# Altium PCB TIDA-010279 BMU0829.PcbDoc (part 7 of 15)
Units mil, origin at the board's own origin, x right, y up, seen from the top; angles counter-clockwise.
Board outline 11269.69 x 4438.98 mil, 4 copper layers (Top Layer, Signal Layer 1, Signal Layer 2, Bottom Layer), stack 61.6 mil thick; 1494 components, 725 nets, 3766 pads, 2728 vias.
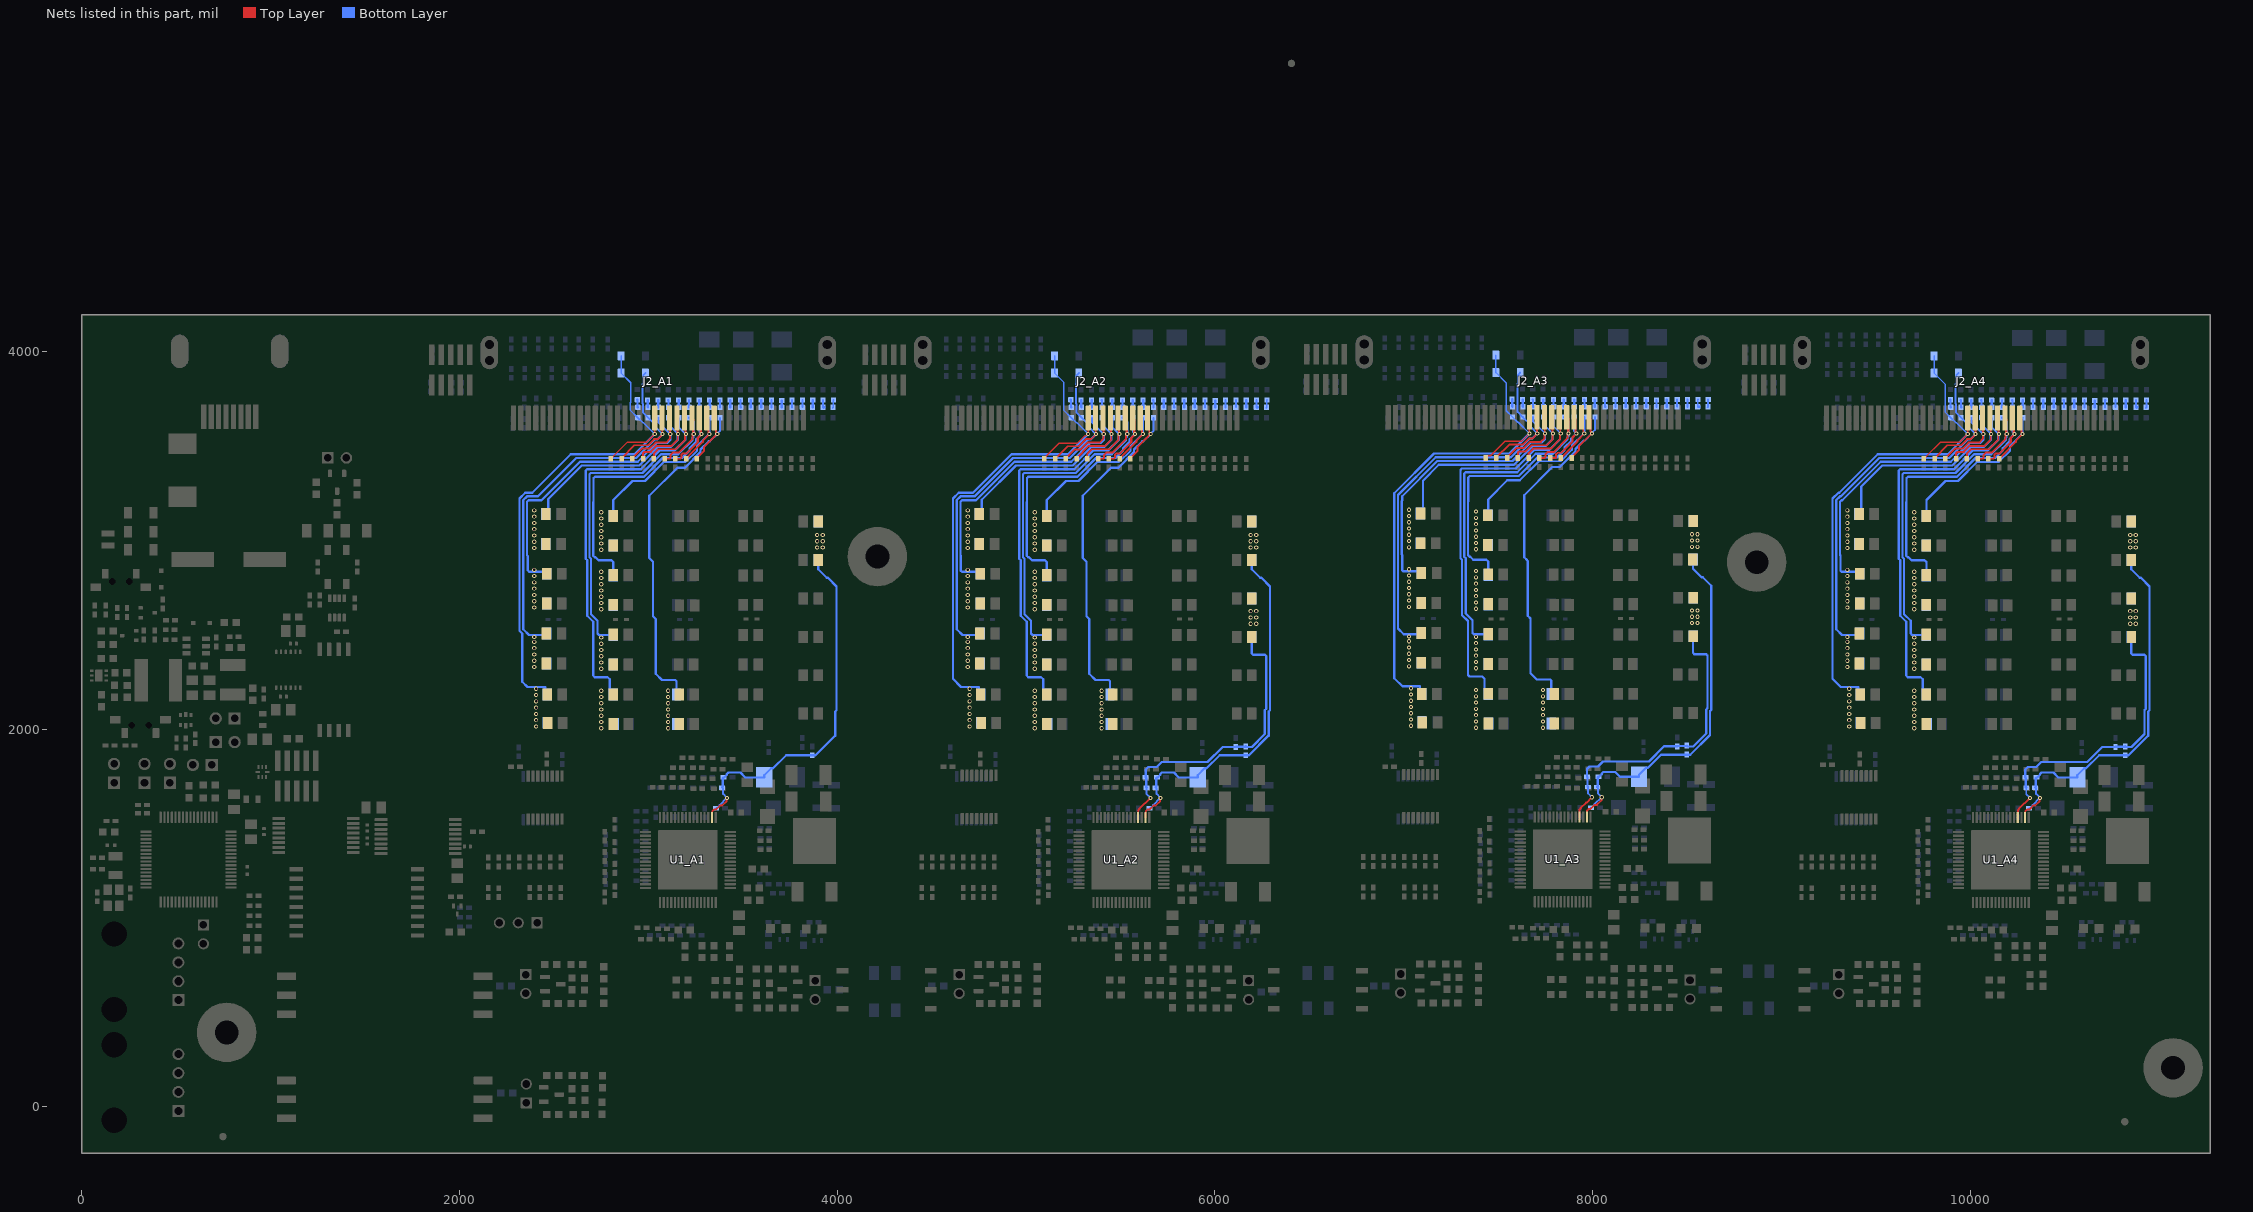
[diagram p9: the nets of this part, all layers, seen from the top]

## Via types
v1: diameter 22.01, hole 12.01, Top Layer to Bottom Layer, tented both sides, 2578 vias
v2: diameter 19.68, hole 7.87, Top Layer to Bottom Layer, tented both sides, 144 vias
v3: diameter 92.52, hole 49.21, Top Layer to Bottom Layer, 4 vias
v4: diameter 19.68, hole 7.87, Top Layer to Bottom Layer, 2 vias

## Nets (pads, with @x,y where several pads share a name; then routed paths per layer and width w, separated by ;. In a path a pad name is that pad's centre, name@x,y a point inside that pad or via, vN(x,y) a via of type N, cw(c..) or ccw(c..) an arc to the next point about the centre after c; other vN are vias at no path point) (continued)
CB17_A2: C4_A2.2 C17_A2.1 R15_A2.2 R18_A2.2 R22_A2.2 R25_A2.2 R198_A2.2 R203_A2.1 U1_A2.4 | length 1594.2
  Top Layer w10: U1_A2.4@5593.07,1531.37 5593.97,1532.27 5593.97,1570.71 5599.59,1576.34 5599.59,1579.06 5628.05,1607.51 5630.77,1607.51 v1(5658.86,1635.6)
  Bottom Layer w10: C4_A2.2@5638.39,1690.14 5638.39,1656.07 v1(5658.86,1635.6)
  Bottom Layer w12: C4_A2.2@5638.39,1690.14 5635.88,1692.66 5635.88,1741.49 C17_A2.1@5633.37,1744.01 5633.37,1785.65 5646.48,1798.76 5691.61,1798.76 5718.36,1825.5 5960.79,1825.5 6040.67,1905.38 R203_A2.1@6110.97,1905.38 6112.65,1907.06 6160.62,1907.06 R198_A2.2@6162.3,1908.75 6162.3,1905 6195.54,1905 6264.19,1973.65 6264.19,2100.78 6271.38,2107.97 6271.38,2386.52 6264.35,2393.55 6201.5,2393.55 6194.47,2400.58 R18_A2.2@6194.47,2488.51
  other v1: 6188.77,2558.04 6218.3,2558.04 6188.77,2591.22 6218.3,2591.22 6188.77,2624.41 6218.3,2624.41
CB17_A3: C4_A3.2 C17_A3.1 R15_A3.2 R18_A3.2 R22_A3.2 R25_A3.2 R198_A3.2 R203_A3.1 U1_A3.4 | length 1594.2
  Top Layer w10: U1_A3.4@7929.66,1534.57 7930.57,1535.48 7930.57,1573.92 7936.19,1579.54 7936.19,1582.27 7964.64,1610.72 7967.37,1610.72 v1(7995.46,1638.81)
  Bottom Layer w10: C4_A3.2@7974.99,1693.35 7974.99,1659.28 v1(7995.46,1638.81)
  Bottom Layer w12: C4_A3.2@7974.99,1693.35 7972.48,1695.86 7972.48,1744.7 C17_A3.1@7969.96,1747.21 7969.96,1788.86 7983.07,1801.96 8028.2,1801.96 8054.95,1828.71 8297.39,1828.71 8377.27,1908.59 R203_A3.1@8447.57,1908.59 8449.25,1910.27 8497.21,1910.27 R198_A3.2@8498.9,1911.96 8498.9,1908.21 8532.14,1908.21 8600.79,1976.86 8600.79,2103.99 8607.98,2111.18 8607.98,2389.73 8600.95,2396.75 8538.09,2396.75 8531.06,2403.78 R18_A3.2@8531.06,2491.72
  other v1: 8525.37,2561.24 8554.9,2561.24 8525.37,2594.43 8554.9,2594.43 8525.37,2627.61 8554.9,2627.61
CB17_A4: C4_A4.2 C17_A4.1 R15_A4.2 R18_A4.2 R22_A4.2 R25_A4.2 R198_A4.2 R203_A4.1 U1_A4.4 | length 1594.2
  Top Layer w10: U1_A4.4@10249.89,1531.37 10250.8,1532.27 10250.8,1570.71 10256.42,1576.34 10256.42,1579.06 10284.87,1607.51 10287.6,1607.51 v1(10315.69,1635.6)
  Bottom Layer w10: C4_A4.2@10295.22,1690.14 10295.22,1656.07 v1(10315.69,1635.6)
  Bottom Layer w12: C4_A4.2@10295.22,1690.14 10292.71,1692.66 10292.71,1741.49 C17_A4.1@10290.19,1744.01 10290.19,1785.65 10303.3,1798.76 10348.43,1798.76 10375.18,1825.5 10617.62,1825.5 10697.5,1905.38 R203_A4.1@10767.8,1905.38 10769.48,1907.06 10817.44,1907.06 R198_A4.2@10819.13,1908.75 10819.13,1905 10852.37,1905 10921.02,1973.65 10921.02,2100.78 10928.21,2107.97 10928.21,2386.52 10921.18,2393.55 10858.32,2393.55 10851.29,2400.58 R18_A4.2@10851.29,2488.51
  other v1: 10845.6,2558.04 10875.13,2558.04 10845.6,2591.22 10875.13,2591.22 10845.6,2624.41 10875.13,2624.41
CB18_A1: C1_A1.1 C4_A1.1 D10_A1.1 R3_A1.2 R6_A1.2 R9_A1.2 R12_A1.2 R198_A1.1 R204_A1.2 U1_A1.2 | length 2044.2
  Top Layer w10: U1_A1.2@3337.42,1531.37 3337.42,1554.99 3338.33,1555.89 3338.33,1565.08 3347.01,1573.77 3358.1,1573.77 3379.79,1595.46 3390.88,1595.46 3414.12,1618.69 3414.12,1633.3 v1(3416.41,1635.6)
  Bottom Layer w10: R204_A1.2@3358.56,1580.59 3362.5,1580.59 3377.18,1595.27 3377.18,1597.73 3415.05,1635.6 v1(3416.41,1635.6) 3395.62,1656.39 3395.62,1685.14 C4_A1.1@3390.62,1690.14
  Bottom Layer w12: C4_A1.1@3390.62,1690.14 3394.32,1693.84 3394.32,1740.32 C1_A1.1@3398.02,1744.01 3401.95,1744.01 3415.64,1757.7 3415.64,1761.57 3423.77,1769.7 3487.57,1769.7 3513.39,1743.88 3613.56,1743.88 D10_A1.1@3613.69,1744.01 3613.69,1755.51 3650.19,1792.01 3660.39,1792.01 3729.88,1861.5 R198_A1.1@3867.28,1861.5 3885.14,1861.5 3989.05,1965.42 3989.05,2092.55 3996.24,2099.74 3996.24,2755.55 3951.17,2800.62 3944.52,2800.62 3899.45,2845.69 R3_A1.2@3899.45,2895.38
  other v1: 3893.76,2961.58 3923.29,2961.58 3893.76,2994.76 3923.29,2994.76 3893.76,3027.95 3923.29,3027.95
CB18_A2: C1_A2.1 C4_A2.1 D10_A2.1 R3_A2.2 R6_A2.2 R9_A2.2 R12_A2.2 R198_A2.1 R204_A2.2 U1_A2.2 | length 2044.2
  Top Layer w10: U1_A2.2@5632.44,1531.37 5632.44,1554.99 5633.34,1555.89 5633.34,1565.08 5642.02,1573.77 5653.12,1573.77 5674.81,1595.46 5685.9,1595.46 5709.13,1618.69 5709.13,1633.3 v1(5711.43,1635.6)
  Bottom Layer w10: R204_A2.2@5653.58,1580.59 5657.51,1580.59 5672.2,1595.27 5672.2,1597.73 5710.07,1635.6 v1(5711.43,1635.6) 5690.64,1656.39 5690.64,1685.14 C4_A2.1@5685.64,1690.14
  Bottom Layer w12: C4_A2.1@5685.64,1690.14 5689.33,1693.84 5689.33,1740.32 C1_A2.1@5693.03,1744.01 5696.97,1744.01 5710.65,1757.7 5710.65,1761.57 5718.78,1769.7 5782.59,1769.7 5808.4,1743.88 5908.58,1743.88 D10_A2.1@5908.7,1744.01 5908.71,1755.51 5945.21,1792.01 5955.41,1792.01 6024.9,1861.5 R198_A2.1@6162.3,1861.5 6180.15,1861.5 6284.06,1965.42 6284.06,2092.55 6291.26,2099.74 6291.26,2755.55 6246.19,2800.62 6239.54,2800.62 6194.47,2845.69 R3_A2.2@6194.47,2895.38
  other v1: 6188.77,2961.58 6218.3,2961.58 6188.77,2994.76 6218.3,2994.76 6188.77,3027.95 6218.3,3027.95
CB18_A3: C1_A3.1 C4_A3.1 D10_A3.1 R3_A3.2 R6_A3.2 R9_A3.2 R12_A3.2 R198_A3.1 R204_A3.2 U1_A3.2 | length 2044.2
  Top Layer w10: U1_A3.2@7969.03,1534.57 7969.03,1558.2 7969.94,1559.1 7969.94,1568.29 7978.62,1576.97 7989.71,1576.97 8011.4,1598.66 8022.5,1598.66 8045.73,1621.9 8045.73,1636.51 v1(8048.03,1638.81)
  Bottom Layer w10: R204_A3.2@7990.17,1583.79 7994.11,1583.79 8008.79,1598.48 8008.79,1600.94 8046.67,1638.81 v1(8048.03,1638.81) 8027.23,1659.6 8027.23,1688.35 C4_A3.1@8022.23,1693.35
  Bottom Layer w12: C4_A3.1@8022.23,1693.35 8025.93,1697.05 8025.93,1743.53 C1_A3.1@8029.63,1747.22 8033.57,1747.22 8047.25,1760.91 8047.25,1764.78 8055.38,1772.91 8119.18,1772.91 8145,1747.09 8245.18,1747.09 D10_A3.1@8245.3,1747.22 8245.31,1758.72 8281.81,1795.22 8292,1795.22 8361.5,1864.71 R198_A3.1@8498.9,1864.71 8516.75,1864.71 8620.66,1968.62 8620.66,2095.76 8627.85,2102.95 8627.85,2758.76 8582.79,2803.83 8576.13,2803.83 8531.06,2848.89 R3_A3.2@8531.06,2898.58
  other v1: 8525.37,2964.79 8554.9,2964.79 8525.37,2997.97 8554.9,2997.97 8525.37,3031.16 8554.9,3031.16
CB18_A4: C1_A4.1 C4_A4.1 D10_A4.1 R3_A4.2 R6_A4.2 R9_A4.2 R12_A4.2 R198_A4.1 R204_A4.2 U1_A4.2 | length 2044.2
  Top Layer w10: U1_A4.2@10289.26,1531.37 10289.26,1554.99 10290.17,1555.89 10290.17,1565.08 10298.85,1573.77 10309.94,1573.77 10331.63,1595.46 10342.73,1595.46 10365.96,1618.69 10365.96,1633.3 v1(10368.26,1635.6)
  Bottom Layer w10: R204_A4.2@10310.4,1580.59 10314.34,1580.59 10329.02,1595.27 10329.02,1597.73 10366.89,1635.6 v1(10368.26,1635.6) 10347.46,1656.39 10347.46,1685.14 C4_A4.1@10342.46,1690.14
  Bottom Layer w12: C4_A4.1@10342.46,1690.14 10346.16,1693.84 10346.16,1740.32 C1_A4.1@10349.86,1744.01 10353.8,1744.01 10367.48,1757.7 10367.48,1761.57 10375.61,1769.7 10439.41,1769.7 10465.23,1743.88 10565.41,1743.88 D10_A4.1@10565.53,1744.01 10565.54,1755.51 10602.04,1792.01 10612.23,1792.01 10681.73,1861.5 R198_A4.1@10819.13,1861.5 10836.98,1861.5 10940.89,1965.42 10940.89,2092.55 10948.08,2099.74 10948.08,2755.55 10903.02,2800.62 10896.36,2800.62 10851.29,2845.69 R3_A4.2@10851.29,2895.38
  other v1: 10845.6,2961.58 10875.13,2961.58 10845.6,2994.76 10875.13,2994.76 10845.6,3027.95 10875.13,3027.95
CCAP_0_A1: C91_A1.2 C92_A1.1 | length 40.9
  Bottom Layer w12: C92_A1.1@2941.7,3743.58 2942.97,3742.31 2942.97,3704.97 C91_A1.2@2944.24,3703.7
CCAP_0_A2: C91_A2.2 C92_A2.1 | length 40.9
  Bottom Layer w12: C92_A2.1@5236.71,3743.58 5237.98,3742.31 5237.98,3704.97 C91_A2.2@5239.25,3703.7
CCAP_0_A3: C91_A3.2 C92_A3.1 | length 40.9
  Bottom Layer w12: C92_A3.1@7573.31,3746.79 7574.58,3745.52 7574.58,3708.17 C91_A3.2@7575.85,3706.9
CCAP_0_A4: C91_A4.2 C92_A4.1 | length 40.9
  Bottom Layer w12: C92_A4.1@9893.54,3743.58 9894.81,3742.31 9894.81,3704.97 C91_A4.2@9896.08,3703.7
CCAP_1_A1: C86_A1.2 C87_A1.1 | length 38.9
  Bottom Layer w12: C87_A1.1@2996.33,3741.61 2997.5,3740.44 2997.5,3704.86 C86_A1.2@2998.67,3703.7
CCAP_1_A2: C86_A2.2 C87_A2.1 | length 38.9
  Bottom Layer w12: C87_A2.1@5291.35,3741.61 5292.52,3740.44 5292.52,3704.86 C86_A2.2@5293.68,3703.7
CCAP_1_A3: C86_A3.2 C87_A3.1 | length 38.9
  Bottom Layer w12: C87_A3.1@7627.94,3744.82 7629.11,3743.65 7629.11,3708.07 C86_A3.2@7630.28,3706.9
CCAP_1_A4: C86_A4.2 C87_A4.1 | length 38.9
  Bottom Layer w12: C87_A4.1@9948.17,3741.61 9949.34,3740.44 9949.34,3704.86 C86_A4.2@9950.51,3703.7
CCAP_2_A1: C82_A1.2 C83_A1.1 | length 38.8
  Bottom Layer w12: C83_A1.1@3050.97,3741.61 3052.03,3740.55 3052.03,3704.76 C82_A1.2@3053.1,3703.7
CCAP_2_A2: C82_A2.2 C83_A2.1 | length 38.8
  Bottom Layer w12: C83_A2.1@5345.98,3741.61 5347.05,3740.55 5347.05,3704.76 C82_A2.2@5348.11,3703.7
CCAP_2_A3: C82_A3.2 C83_A3.1 | length 38.8
  Bottom Layer w12: C83_A3.1@7682.58,3744.82 7683.65,3743.75 7683.65,3707.97 C82_A3.2@7684.71,3706.9
CCAP_2_A4: C82_A4.2 C83_A4.1 | length 38.8
  Bottom Layer w12: C83_A4.1@10002.81,3741.61 10003.88,3740.55 10003.88,3704.76 C82_A4.2@10004.94,3703.7
CCAP_3_A1: C77_A1.2 C78_A1.1 | length 38.7
  Bottom Layer w12: C78_A1.1@3105.6,3741.61 3106.57,3740.65 3106.57,3704.66 C77_A1.2@3107.53,3703.7
CCAP_3_A2: C77_A2.2 C78_A2.1 | length 38.7
  Bottom Layer w12: C78_A2.1@5400.62,3741.61 5401.58,3740.65 5401.58,3704.66 C77_A2.2@5402.54,3703.7
CCAP_3_A3: C77_A3.2 C78_A3.1 | length 38.7
  Bottom Layer w12: C78_A3.1@7737.21,3744.82 7738.18,3743.86 7738.18,3707.87 C77_A3.2@7739.14,3706.9
CCAP_3_A4: C77_A4.2 C78_A4.1 | length 38.7
  Bottom Layer w12: C78_A4.1@10057.44,3741.61 10058.41,3740.65 10058.41,3704.66 C77_A4.2@10059.37,3703.7
CCAP_4_A1: C69_A1.2 C70_A1.1 | length 38.6
  Bottom Layer w12: C70_A1.1@3160.24,3741.61 3161.1,3740.75 3161.1,3704.56 C69_A1.2@3161.96,3703.7
CCAP_4_A2: C69_A2.2 C70_A2.1 | length 38.6
  Bottom Layer w12: C70_A2.1@5455.25,3741.61 5456.11,3740.75 5456.11,3704.56 C69_A2.2@5456.97,3703.7
CCAP_4_A3: C69_A3.2 C70_A3.1 | length 38.6
  Bottom Layer w12: C70_A3.1@7791.85,3744.82 7792.71,3743.96 7792.71,3707.77 C69_A3.2@7793.57,3706.9
CCAP_4_A4: C69_A4.2 C70_A4.1 | length 38.6
  Bottom Layer w12: C70_A4.1@10112.08,3741.61 10112.94,3740.75 10112.94,3704.56 C69_A4.2@10113.8,3703.7
CCAP_5_A1: C65_A1.2 C66_A1.1 | length 38.5
  Bottom Layer w12: C66_A1.1@3214.87,3741.61 3215.63,3740.85 3215.63,3704.45 C65_A1.2@3216.39,3703.7
CCAP_5_A2: C65_A2.2 C66_A2.1 | length 38.5
  Bottom Layer w12: C66_A2.1@5509.89,3741.61 5510.65,3740.85 5510.65,3704.45 C65_A2.2@5511.41,3703.7
CCAP_5_A3: C65_A3.2 C66_A3.1 | length 38.5
  Bottom Layer w12: C66_A3.1@7846.48,3744.82 7847.24,3744.06 7847.24,3707.66 C65_A3.2@7848,3706.9
CCAP_5_A4: C65_A4.2 C66_A4.1 | length 38.5
  Bottom Layer w12: C66_A4.1@10166.71,3741.61 10167.47,3740.85 10167.47,3704.45 C65_A4.2@10168.23,3703.7
CCAP_6_A1: C59_A1.2 C60_A1.1 | length 38.5
  Bottom Layer w12: C60_A1.1@3269.51,3741.61 3270.16,3740.95 3270.16,3704.35 C59_A1.2@3270.82,3703.7
CCAP_6_A2: C59_A2.2 C60_A2.1 | length 38.5
  Bottom Layer w12: C60_A2.1@5564.52,3741.61 5565.18,3740.95 5565.18,3704.35 C59_A2.2@5565.84,3703.7
CCAP_6_A3: C59_A3.2 C60_A3.1 | length 38.5
  Bottom Layer w12: C60_A3.1@7901.12,3744.82 7901.78,3744.16 7901.78,3707.56 C59_A3.2@7902.43,3706.9
CCAP_6_A4: C59_A4.2 C60_A4.1 | length 38.5
  Bottom Layer w12: C60_A4.1@10221.35,3741.61 10222,3740.95 10222,3704.35 C59_A4.2@10222.66,3703.7
CCAP_7_A1: C56_A1.2 C57_A1.1 | length 38.4
  Bottom Layer w12: C57_A1.1@3324.14,3741.61 3324.7,3741.06 3324.7,3704.25 C56_A1.2@3325.25,3703.7
CCAP_7_A2: C56_A2.2 C57_A2.1 | length 38.4
  Bottom Layer w12: C57_A2.1@5619.16,3741.61 5619.71,3741.06 5619.71,3704.25 C56_A2.2@5620.27,3703.7
CCAP_7_A3: C56_A3.2 C57_A3.1 | length 38.4
  Bottom Layer w12: C57_A3.1@7955.75,3744.82 7956.31,3744.26 7956.31,3707.46 C56_A3.2@7956.86,3706.9
CCAP_7_A4: C56_A4.2 C57_A4.1 | length 38.4
  Bottom Layer w12: C57_A4.1@10275.98,3741.61 10276.54,3741.06 10276.54,3704.25 C56_A4.2@10277.09,3703.7
CCAP_8_A1: C50_A1.2 C51_A1.1 | length 38.3
  Bottom Layer w12: C51_A1.1@3378.77,3741.61 3379.23,3741.16 3379.23,3704.15 C50_A1.2@3379.68,3703.7
CCAP_8_A2: C50_A2.2 C51_A2.1 | length 38.3
  Bottom Layer w12: C51_A2.1@5673.79,3741.61 5674.24,3741.16 5674.24,3704.15 C50_A2.2@5674.7,3703.7
CCAP_8_A3: C50_A3.2 C51_A3.1 | length 38.3
  Bottom Layer w12: C51_A3.1@8010.39,3744.82 8010.84,3744.37 8010.84,3707.36 C50_A3.2@8011.29,3706.9
CCAP_8_A4: C50_A4.2 C51_A4.1 | length 38.3
  Bottom Layer w12: C51_A4.1@10330.62,3741.61 10331.07,3741.16 10331.07,3704.15 C50_A4.2@10331.52,3703.7
CCAP_9_A1: C47_A1.2 C48_A1.1 | length 38.3
  Bottom Layer w12: C48_A1.1@3433.41,3741.61 3433.85,3741.17 3433.85,3704.14 C47_A1.2@3434.3,3703.7
CCAP_9_A2: C47_A2.2 C48_A2.1 | length 38.3
  Bottom Layer w12: C48_A2.1@5728.42,3741.61 5728.87,3741.17 5728.87,3704.14 C47_A2.2@5729.31,3703.7
CCAP_9_A3: C47_A3.2 C48_A3.1 | length 38.3
  Bottom Layer w12: C48_A3.1@8065.02,3744.82 8065.47,3744.38 8065.47,3707.35 C47_A3.2@8065.91,3706.9
CCAP_9_A4: C47_A4.2 C48_A4.1 | length 38.3
  Bottom Layer w12: C48_A4.1@10385.25,3741.61 10385.7,3741.17 10385.7,3704.14 C47_A4.2@10386.14,3703.7
CCAP_10_A1: C42_A1.2 C43_A1.1 | length 38
  Bottom Layer w12: C43_A1.1@3542.68,3741.61 3542.82,3741.46 3542.82,3703.84 C42_A1.2@3542.97,3703.7
CCAP_10_A2: C42_A2.2 C43_A2.1 | length 38
  Bottom Layer w12: C43_A2.1@5837.69,3741.61 5837.84,3741.46 5837.84,3703.84 C42_A2.2@5837.99,3703.7
CCAP_10_A3: C42_A3.2 C43_A3.1 | length 38
  Bottom Layer w12: C43_A3.1@8174.29,3744.82 8174.44,3744.67 8174.44,3707.05 C42_A3.2@8174.58,3706.9
CCAP_10_A4: C42_A4.2 C43_A4.1 | length 38
  Bottom Layer w12: C43_A4.1@10494.52,3741.61 10494.67,3741.46 10494.67,3703.84 C42_A4.2@10494.81,3703.7
CCAP_11_A1: C39_A1.2 C40_A1.1 | length 38
  Bottom Layer w12: C40_A1.1@3597.31,3741.61 3597.36,3741.57 C39_A1.2@3597.4,3703.7 C39_A1.2@3597.4,3703.7
CCAP_11_A2: C39_A2.2 C40_A2.1 | length 38
  Bottom Layer w12: C40_A2.1@5892.33,3741.61 5892.37,3741.57 C39_A2.2@5892.42,3703.7 C39_A2.2@5892.42,3703.7
CCAP_11_A3: C39_A3.2 C40_A3.1 | length 38
  Bottom Layer w12: C39_A3.2@8229.01,3706.9 C39_A3.2@8229.01,3706.9 C40_A3.1@8228.97,3744.78 ; C40_A3.1@8228.93,3744.82 C40_A3.1@8228.97,3744.78
CCAP_11_A4: C39_A4.2 C40_A4.1 | length 38
  Bottom Layer w12: C40_A4.1@10549.16,3741.61 C40_A4.1@10549.16,3741.61 C39_A4.2@10549.24,3703.7 C39_A4.2@10549.24,3703.7
CCAP_12_A1: C31_A1.2 C32_A1.1 | length 38
  Bottom Layer w12: C31_A1.2@3651.83,3703.7 3651.89,3703.75 C32_A1.1@3651.95,3741.61 C32_A1.1@3651.95,3741.61
CCAP_12_A2: C31_A2.2 C32_A2.1 | length 38
  Bottom Layer w12: C31_A2.2@5946.85,3703.7 5946.91,3703.75 5946.91,3741.55 C32_A2.1@5946.96,3741.61
CCAP_12_A3: C31_A3.2 C32_A3.1 | length 38
  Bottom Layer w12: C31_A3.2@8283.44,3706.9 8283.5,3706.96 8283.5,3744.76 C32_A3.1@8283.56,3744.82
CCAP_12_A4: C31_A4.2 C32_A4.1 | length 38
  Bottom Layer w12: C31_A4.2@10603.67,3703.7 10603.73,3703.75 10603.73,3741.55 C32_A4.1@10603.79,3741.61
CCAP_13_A1: C27_A1.2 C28_A1.1 | length 36.1
  Bottom Layer w12: C27_A1.2@3706.26,3703.7 3706.42,3703.86 3706.42,3739.48 C28_A1.1@3706.58,3739.64
CCAP_13_A2: C27_A2.2 C28_A2.1 | length 36.1
  Bottom Layer w12: C27_A2.2@6001.28,3703.7 6001.44,3703.86 6001.44,3739.48 C28_A2.1@6001.6,3739.64
CCAP_13_A3: C27_A3.2 C28_A3.1 | length 36.1
  Bottom Layer w12: C27_A3.2@8337.88,3706.9 8338.03,3707.06 8338.03,3742.69 C28_A3.1@8338.19,3742.85
CCAP_13_A4: C27_A4.2 C28_A4.1 | length 36.1
  Bottom Layer w12: C27_A4.2@10658.11,3703.7 10658.26,3703.86 10658.26,3739.48 C28_A4.1@10658.42,3739.64
CCAP_14_A1: C23_A1.2 C24_A1.1 | length 38.1
  Bottom Layer w12: C23_A1.2@3760.69,3703.7 3760.95,3703.96 3760.95,3741.35 C24_A1.1@3761.22,3741.61
CCAP_14_A2: C23_A2.2 C24_A2.1 | length 38.1
  Bottom Layer w12: C23_A2.2@6055.71,3703.7 6055.97,3703.96 6055.97,3741.35 C24_A2.1@6056.23,3741.61
CCAP_14_A3: C23_A3.2 C24_A3.1 | length 38.1
  Bottom Layer w12: C23_A3.2@8392.31,3706.9 8392.57,3707.17 8392.57,3744.56 C24_A3.1@8392.83,3744.82
CCAP_14_A4: C23_A4.2 C24_A4.1 | length 38.1
  Bottom Layer w12: C23_A4.2@10712.54,3703.7 10712.8,3703.96 10712.8,3741.35 C24_A4.1@10713.06,3741.61
CCAP_15_A1: C19_A1.2 C20_A1.1 | length 38.2
  Bottom Layer w10: C19_A1.2@3815.12,3703.7 3815.49,3704.06 3815.49,3741.25 C20_A1.1@3815.85,3741.61
CCAP_15_A2: C19_A2.2 C20_A2.1 | length 38.2
  Bottom Layer w10: C19_A2.2@6110.14,3703.7 6110.5,3704.06 6110.5,3741.25 C20_A2.1@6110.87,3741.61
CCAP_15_A3: C19_A3.2 C20_A3.1 | length 38.2
  Bottom Layer w10: C19_A3.2@8446.74,3706.9 8447.1,3707.27 8447.1,3744.46 C20_A3.1@8447.46,3744.82
CCAP_15_A4: C19_A4.2 C20_A4.1 | length 38.2
  Bottom Layer w10: C19_A4.2@10766.97,3703.7 10767.33,3704.06 10767.33,3741.25 C20_A4.1@10767.69,3741.61
CCAP_16_A1: C11_A1.2 C12_A1.1 | length 38.3
  Bottom Layer w12: C11_A1.2@3869.55,3703.7 3870.02,3704.16 3870.02,3741.15 C12_A1.1@3870.49,3741.61
CCAP_16_A2: C11_A2.2 C12_A2.1 | length 38.3
  Bottom Layer w12: C11_A2.2@6164.57,3703.7 6165.04,3704.16 6165.04,3741.15 C12_A2.1@6165.5,3741.61
CCAP_16_A3: C11_A3.2 C12_A3.1 | length 38.3
  Bottom Layer w12: C11_A3.2@8501.17,3706.9 8501.63,3707.37 8501.63,3744.35 C12_A3.1@8502.1,3744.82
CCAP_16_A4: C11_A4.2 C12_A4.1 | length 38.3
  Bottom Layer w12: C11_A4.2@10821.4,3703.7 10821.86,3704.16 10821.86,3741.15 C12_A4.1@10822.33,3741.61
CCAP_17_A1: C8_A1.2 C9_A1.1 | length 47.1
  Bottom Layer w10: C9_A1.1@3925.12,3741.61 3924.55,3741.04 3924.55,3703.4 C8_A1.2@3927.17,3700.79
  Bottom Layer w12: C8_A1.2@3927.17,3703.7 C8_A1.2@3932.1,3703.7
CCAP_17_A2: C8_A2.2 C9_A2.1 | length 47.1
  Bottom Layer w10: C9_A2.1@6220.14,3741.61 6219.57,3741.04 6219.57,3703.4 C8_A2.2@6222.18,3700.79
  Bottom Layer w12: C8_A2.2@6222.18,3703.7 C8_A2.2@6227.12,3703.7
CCAP_17_A3: C8_A3.2 C9_A3.1 | length 47.1
  Bottom Layer w10: C9_A3.1@8556.73,3744.82 8556.17,3744.25 8556.17,3706.61 C8_A3.2@8558.78,3704
  Bottom Layer w12: C8_A3.2@8558.78,3706.9 C8_A3.2@8563.71,3706.9
CCAP_17_A4: C8_A4.2 C9_A4.1 | length 47.1
  Bottom Layer w10: C9_A4.1@10876.96,3741.61 10876.4,3741.04 10876.4,3703.4 C8_A4.2@10879.01,3700.79
  Bottom Layer w12: C8_A4.2@10879.01,3703.7 C8_A4.2@10883.94,3703.7
CCAP_18_A1: C5_A1.2 C6_A1.1 | length 42.2
  Bottom Layer w10: C5_A1.2@3976.38,3700.79 3979.09,3703.49 3979.09,3740.94 C6_A1.1@3979.76,3741.61
CCAP_18_A2: C5_A2.2 C6_A2.1 | length 42.2
  Bottom Layer w10: C5_A2.2@6271.39,3700.79 6274.1,3703.49 6274.1,3740.94 C6_A2.1@6274.77,3741.61
CCAP_18_A3: C5_A3.2 C6_A3.1 | length 42.2
  Bottom Layer w10: C5_A3.2@8607.99,3704 8610.7,3706.7 8610.7,3744.15 C6_A3.1@8611.37,3744.82
CCAP_18_A4: C5_A4.2 C6_A4.1 | length 42.2
  Bottom Layer w10: C5_A4.2@10928.22,3700.79 10930.93,3703.49 10930.93,3740.94 C6_A4.1@10931.6,3741.61
CCAP_BB_A1: C99_A1.2 C100_A1.1 | length 38.2
  Bottom Layer w12: C100_A1.1@3488.04,3741.61 3488.4,3741.26 3488.4,3704.05 C99_A1.2@3488.75,3703.7
CCAP_BB_A2: C99_A2.2 C100_A2.1 | length 38.2
  Bottom Layer w12: C100_A2.1@5783.06,3741.61 5783.41,3741.26 5783.41,3704.05 C99_A2.2@5783.76,3703.7
CCAP_BB_A3: C99_A3.2 C100_A3.1 | length 38.2
  Bottom Layer w12: C100_A3.1@8119.66,3744.82 8120.01,3744.47 8120.01,3707.26 C99_A3.2@8120.36,3706.9
CCAP_BB_A4: C99_A4.2 C100_A4.1 | length 38.2
  Bottom Layer w12: C100_A4.1@10439.89,3741.61 10440.24,3741.26 10440.24,3704.05 C99_A4.2@10440.59,3703.7
CELL0_A1: C91_A1.1 D4_A1.1 D5_A1.2 J2_A1.10 R84_A1.1 R85_A1.1 R86_A1.1 R87_A1.1 R139_A1.1 | length 2876.5
  Top Layer w8: R139_A1.1@2801.57,3431.26 2801.57,3435.19 2809.38,3443 2813.32,3443 2890.25,3519.93 2991.69,3519.93 v1(3033.57,3561.81) J2_A1.10@3033.57,3647.12
  Bottom Layer w8: D4_A1.1@2855.6,3976.38 D5_A1.2@2855.6,3884.6 2906.73,3833.48 2906.73,3730.67 2903.54,3727.49 2903.54,3689.27 C91_A1.1@2944.24,3648.58 2971.36,3621.45 2974.24,3621.45 3033.57,3562.12 v1(3033.57,3561.81)
  Bottom Layer w12: R85_A1.1@2464.54,2183.48 2454.14,2193.88 2454.14,2223.14 2360.77,2223.14 2332.68,2251.23 2332.68,2505.74 2317.45,2520.97 2317.45,3220.53 2348.86,3251.94 2385.8,3251.94 2589.49,3455.63 2927.39,3455.63 v1(3033.57,3561.81)
  other v1: 2406.08,2014.09 2406.08,2047.28 2406.08,2080.46 2406.08,2113.65 2406.08,2146.83 2406.08,2180.02 2406.08,2213.2
CELL0_A2: C91_A2.1 D4_A2.1 D5_A2.2 J2_A2.10 R84_A2.1 R85_A2.1 R86_A2.1 R87_A2.1 R139_A2.1 | length 2875
  Top Layer w8: R139_A2.1@5096.59,3431.26 5096.59,3435.19 5175.79,3514.4 5271.98,3514.4 5309.56,3551.98 5314.96,3551.98 5324.8,3561.81 v1(5328.59,3561.81) J2_A2.10@5328.59,3647.12
  Bottom Layer w8: D4_A2.1@5150.62,3976.38 D5_A2.2@5150.62,3884.6 5200.03,3835.19 5200.03,3730.67 5198.56,3729.2 5198.56,3689.27 C91_A2.1@5239.25,3648.58 5266.38,3621.45 5269.25,3621.45 5328.59,3562.12 v1(5328.59,3561.81)
  Bottom Layer w12: R85_A2.1@4759.55,2183.48 4749.15,2193.88 4749.15,2223.14 4655.78,2223.14 4612.46,2266.46 4612.46,3220.53 4643.87,3251.94 4718.48,3251.94 4922.17,3455.63 5222.41,3455.63 v1(5328.59,3561.81)
  other v1: 4701.1,2014.09 4701.1,2047.28 4701.1,2080.46 4701.1,2113.65 4701.1,2146.83 4701.1,2180.02 4701.1,2213.2
CELL0_A3: C91_A3.1 D4_A3.1 D5_A3.2 J2_A3.10 R84_A3.1 R85_A3.1 R86_A3.1 R87_A3.1 R139_A3.1 | length 2888.4
  Top Layer w8: R139_A3.1@7433.19,3434.46 7433.19,3438.4 7441,3446.21 7457.45,3446.21 7534.38,3523.14 7623.3,3523.14 v1(7665.18,3565.02) J2_A3.10@7665.18,3650.33
  Bottom Layer w8: D4_A3.1@7487.22,3979.59 D5_A3.2@7487.22,3887.81 7542.56,3832.46 7542.56,3685.07 C91_A3.1@7575.85,3651.79 7602.98,3624.66 7605.85,3624.66 7665.18,3565.33 v1(7665.18,3565.02)
  Bottom Layer w12: R85_A3.1@7096.15,2186.69 7085.75,2197.08 7085.75,2226.35 6992.38,2226.35 6949.06,2269.67 6949.06,3248.69 7159.21,3458.84 7559,3458.84 v1(7665.18,3565.02)
  other v1: 7037.69,2017.3 7037.69,2050.49 7037.69,2083.67 7037.69,2116.86 7037.69,2150.04 7037.69,2183.23 7037.69,2216.41
CELL0_A4: C91_A4.1 D4_A4.1 D5_A4.2 J2_A4.10 R84_A4.1 R85_A4.1 R86_A4.1 R87_A4.1 R139_A4.1 | length 2873.8
  Top Layer w8: R139_A4.1@9753.42,3431.26 9753.42,3435.19 9761.23,3443 9765.16,3443 9842.09,3519.93 9943.53,3519.93 v1(9985.41,3561.81) J2_A4.10@9985.41,3647.12
  Bottom Layer w8: D4_A4.1@9807.45,3976.38 D5_A4.2@9807.45,3884.6 9865.4,3826.65 9865.4,3679.26 C91_A4.1@9896.08,3648.58 9923.21,3621.45 9926.08,3621.45 9985.41,3562.12 v1(9985.41,3561.81)
  Bottom Layer w12: R85_A4.1@9416.38,2183.48 9405.98,2193.88 9405.98,2223.14 9312.61,2223.14 9269.29,2266.46 9269.29,3220.53 9300.7,3251.94 9305.09,3251.94 9508.78,3455.63 9879.23,3455.63 v1(9985.41,3561.81)
  other v1: 9357.92,2014.09 9357.92,2047.28 9357.92,2080.46 9357.92,2113.65 9357.92,2146.83 9357.92,2180.02 9357.92,2213.2
CELL1_A1: C86_A1.1 D5_A1.1 J2_A1.31 R69_A1.1 R72_A1.1 R76_A1.1 R80_A1.1 R138_A1.1 | length 2499.5
  Top Layer w8: J2_A1.31@3072.94,3595.94 J2_A1.31@3072.94,3647.12
  Top Layer w10: R138_A1.1@2858.44,3431.26 2858.44,3435.19 2926.3,3503.06 2998.68,3503.06 3030.73,3535.11 3048.66,3535.11 v1@3075.15,3561.6 ; J2_A1.31@3072.94,3647.12 3073.94,3646.13 3073.94,3562.81 v1(3074.93,3561.81)
  Bottom Layer w10: D5_A1.1@2984.34,3884.6 2972.82,3873.08 2972.82,3829.44 2969.68,3826.29 2969.68,3723.63 2970.89,3722.42 2970.89,3676.35 C86_A1.1@2998.67,3648.58 3039.23,3608.02 3039.23,3597.52 v1(3074.93,3561.81)
  Bottom Layer w12: v1(2396.24,2486.96) 2396.24,2498.57 ; R72_A1.1@2461.39,2505.07 2454.89,2498.57 2396.24,2498.57 ; v1@3075.15,3561.6 3048.66,3535.11 3034.97,3535.11 2935.62,3435.76 2618.83,3435.76 2415.14,3232.07 2357.09,3232.07 2337.32,3212.3 2337.32,2529.2 2367.95,2498.57 2396.24,2498.57
  other v1: 2396.24,2329.05 2396.24,2362.24 2396.24,2395.42 2396.24,2428.61 2396.24,2461.79
CELL1_A2: C86_A2.1 D5_A2.1 J2_A2.31 R69_A2.1 R72_A2.1 R76_A2.1 R80_A2.1 R138_A2.1 | length 2499.5
  Top Layer w8: J2_A2.31@5367.96,3595.94 J2_A2.31@5367.96,3647.12
  Top Layer w10: R138_A2.1@5153.46,3431.26 5153.46,3435.19 5160.27,3442 5164.2,3442 5219.72,3497.52 5278.97,3497.52 5316.55,3535.11 5343.68,3535.11 v1@5370.17,3561.6 ; J2_A2.31@5367.96,3647.12 5368.95,3646.13 5368.95,3595.94 5368.95,3562.81 v1(5369.95,3561.81)
  Bottom Layer w10: D5_A2.1@5279.36,3884.6 5267.84,3873.08 5267.84,3829.44 5264.69,3826.29 5264.69,3723.63 5265.91,3722.42 5265.91,3676.35 C86_A2.1@5293.68,3648.58 5334.25,3608.02 5334.25,3597.52 v1(5369.95,3561.81)
  Bottom Layer w12: v1(4691.26,2486.96) 4691.26,2498.57 ; R72_A2.1@4756.41,2505.07 4749.91,2498.57 4691.26,2498.57 ; v1@5370.17,3561.6 5343.68,3535.11 5329.99,3535.11 5230.64,3435.76 4930.4,3435.76 4726.71,3232.07 4652.11,3232.07 4632.34,3212.3 4632.34,2529.2 4662.97,2498.57 4691.26,2498.57
  other v1: 4691.26,2329.05 4691.26,2362.24 4691.26,2395.42 4691.26,2428.61 4691.26,2461.79
CELL1_A3: C86_A3.1 D5_A3.1 J2_A3.31 R69_A3.1 R72_A3.1 R76_A3.1 R80_A3.1 R138_A3.1 | length 2513.3
  Top Layer w8: J2_A3.31@7704.55,3599.15 J2_A3.31@7704.55,3650.33
  Top Layer w10: R138_A3.1@7490.05,3434.46 7490.05,3438.4 7557.92,3506.26 7630.29,3506.26 7662.34,3538.32 7680.27,3538.32 v1@7706.76,3564.81 ; J2_A3.31@7704.55,3650.33 7705.55,3649.34 7705.55,3566.02 v1(7706.55,3565.02)
  Bottom Layer w10: D5_A3.1@7615.96,3887.81 7604.44,3876.29 7604.44,3832.64 7601.29,3829.5 7601.29,3726.84 7602.5,3725.63 7602.5,3679.56 C86_A3.1@7630.28,3651.79 7670.84,3611.22 7670.84,3600.73 v1(7706.55,3565.02)
  Bottom Layer w12: v1(7027.85,2490.17) 7027.85,2501.78 ; R72_A3.1@7093.01,2508.28 7086.51,2501.78 7027.85,2501.78 ; v1@7706.76,3564.81 7680.27,3538.32 7666.58,3538.32 7567.24,3438.97 7168.72,3438.97 6968.93,3239.18 6968.93,2532.41 6999.56,2501.78 7027.85,2501.78
  other v1: 7027.85,2332.26 7027.85,2365.45 7027.85,2398.63 7027.85,2431.82 7027.85,2465
CELL1_A4: C86_A4.1 D5_A4.1 J2_A4.31 R69_A4.1 R72_A4.1 R76_A4.1 R80_A4.1 R138_A4.1 | length 2499.5
  Top Layer w8: J2_A4.31@10024.78,3595.94 J2_A4.31@10024.78,3647.12
  Top Layer w10: R138_A4.1@9810.28,3431.26 9810.28,3435.19 9878.15,3503.06 9950.52,3503.06 9982.57,3535.11 10000.5,3535.11 v1@10026.99,3561.6 ; J2_A4.31@10024.78,3647.12 10025.78,3646.13 10025.78,3562.81 v1(10026.78,3561.81)
  Bottom Layer w10: D5_A4.1@9936.19,3884.6 9924.67,3873.08 9924.67,3829.44 9921.52,3826.29 9921.52,3723.63 9922.73,3722.42 9922.73,3676.35 C86_A4.1@9950.51,3648.58 9991.07,3608.02 9991.07,3597.52 v1(10026.78,3561.81)
  Bottom Layer w12: v1(9348.08,2486.96) 9348.08,2498.57 ; R72_A4.1@9413.24,2505.07 9406.74,2498.57 9348.08,2498.57 ; v1@10026.99,3561.6 10000.5,3535.11 9986.81,3535.11 9887.47,3435.76 9517.02,3435.76 9313.32,3232.07 9308.93,3232.07 9289.16,3212.3 9289.16,2529.2 9319.79,2498.57 9348.08,2498.57
  other v1: 9348.08,2329.05 9348.08,2362.24 9348.08,2395.42 9348.08,2428.61 9348.08,2461.79
CELL2_A1: C82_A1.1 J2_A1.11 R55_A1.1 R58_A1.1 R62_A1.1 R66_A1.1 R135_A1.1 | length 1881.1
  Top Layer w10: R135_A1.1@2915.31,3431.26 2915.31,3435.19 2965.3,3485.18 3006.08,3485.18 3038.13,3517.23 3093.6,3517.23 3113.91,3537.54 3113.91,3560.99 v1@3115.51,3562.59 ; J2_A1.11@3103.53,3638.34 J2_A1.11@3112.31,3647.12 3114.3,3645.13 3114.3,3563.81 v1@3115.51,3562.59 ; v1(3116.3,3561.81) v1@3115.51,3562.59
  Bottom Layer w10: C82_A1.1@3053.1,3648.58 3053.1,3625.01 v1(3116.3,3561.81)
  Bottom Layer w12: R58_A1.1@2461.39,2822.4 2451.25,2832.54 2369.23,2832.54 2362.2,2839.57 2362.2,2916.42 2357.19,2921.43 2357.19,3204.07 2365.32,3212.19 2434.64,3212.19 2638.33,3415.89 2943.86,3415.89 3043.2,3515.23 3100.39,3515.23 3116.2,3531.05 v1@3116.2,3561.81
  other v1: 2396.24,2644.02 2396.24,2677.2 2396.24,2710.38 2396.24,2743.57 2396.24,2776.75 2396.24,2809.94 2396.24,2843.12
CELL2_A2: C82_A2.1 J2_A2.11 R55_A2.1 R58_A2.1 R62_A2.1 R66_A2.1 R135_A2.1 | length 1870.9
  Top Layer w10: R135_A2.1@5210.32,3431.26 5210.32,3435.19 5254.78,3479.65 5286.37,3479.65 5323.95,3517.23 5388.62,3517.23 5408.92,3537.54 5408.92,3560.99 v1@5410.53,3562.59 ; J2_A2.11@5407.33,3647.12 5409.32,3645.13 5409.32,3563.81 v1@5410.53,3562.59 ; v1(5411.31,3561.81) v1@5410.53,3562.59
  Bottom Layer w10: C82_A2.1@5348.11,3648.58 5348.11,3625.01 v1(5411.31,3561.81)
  Bottom Layer w12: R58_A2.1@4756.41,2822.4 4746.27,2832.54 4660.46,2832.54 4654.6,2838.4 4654.6,2919.04 4652.21,2921.43 4652.21,3204.07 4660.34,3212.19 4734.94,3212.19 4938.63,3415.89 5238.87,3415.89 5338.22,3515.23 5395.41,3515.23 5411.22,3531.05 v1@5411.22,3561.81
  other v1: 4691.26,2644.02 4691.26,2677.2 4691.26,2710.38 4691.26,2743.57 4691.26,2776.75 4691.26,2809.94 4691.26,2843.12
CELL2_A3: C82_A3.1 J2_A3.11 R55_A3.1 R58_A3.1 R62_A3.1 R66_A3.1 R135_A3.1 | length 1897.1
  Top Layer w10: R135_A3.1@7546.92,3434.46 7546.92,3438.4 7596.91,3488.39 7637.69,3488.39 7669.74,3520.44 7725.22,3520.44 7745.52,3540.75 7745.52,3564.2 v1@7747.13,3565.8 ; J2_A3.11@7735.14,3641.55 J2_A3.11@7743.92,3650.33 7745.92,3648.34 7745.92,3567.01 v1@7747.13,3565.8 ; v1(7747.91,3565.02) v1@7747.13,3565.8
  Bottom Layer w10: C82_A3.1@7684.71,3651.79 7684.71,3628.22 v1(7747.91,3565.02)
  Bottom Layer w12: R58_A3.1@7093.01,2825.61 7082.87,2835.75 6997.05,2835.75 6991.2,2841.61 6991.2,2922.25 6988.81,2924.64 6988.81,3207.28 6991.2,3209.66 6991.2,3233.34 7176.95,3419.09 7575.47,3419.09 7674.82,3518.44 7732,3518.44 7747.82,3534.26 v1@7747.82,3565.02
  other v1: 7027.85,2647.22 7027.85,2680.41 7027.85,2713.59 7027.85,2746.78 7027.85,2779.96 7027.85,2813.15 7027.85,2846.33
CELL2_A4: C82_A4.1 J2_A4.11 R55_A4.1 R58_A4.1 R62_A4.1 R66_A4.1 R135_A4.1 | length 1883.3
  Top Layer w10: R135_A4.1@9867.15,3431.26 9867.15,3435.19 9917.14,3485.18 9957.92,3485.18 9989.97,3517.23 10045.44,3517.23 10065.75,3537.54 10065.75,3560.99 v1@10067.36,3562.59 ; J2_A4.11@10055.37,3638.34 J2_A4.11@10064.15,3647.12 10066.15,3645.13 10066.15,3563.81 v1@10067.36,3562.59 ; v1(10068.14,3561.81) v1@10067.36,3562.59
  Bottom Layer w10: C82_A4.1@10004.94,3648.58 10004.94,3625.01 v1(10068.14,3561.81)
  Bottom Layer w12: R58_A4.1@9413.24,2822.4 9403.1,2832.54 9317.28,2832.54 9311.43,2838.4 9311.43,2919.04 9309.04,2921.43 9309.04,3204.07 9317.16,3212.19 9321.56,3212.19 9525.25,3415.89 9895.7,3415.89 9995.05,3515.23 10052.23,3515.23 10068.05,3531.05 v1@10068.05,3561.81
  other v1: 9348.08,2644.02 9348.08,2677.2 9348.08,2710.38 9348.08,2743.57 9348.08,2776.75 9348.08,2809.94 9348.08,2843.12
CELL3_A1: C77_A1.1 J2_A1.32 R42_A1.1 R45_A1.1 R48_A1.1 R52_A1.1 R132_A1.1 | length 1401.2
  Top Layer w10: R132_A1.1@2972.18,3431.26 2972.18,3461.45 2978.03,3467.31 3013.48,3467.31 3045.54,3499.36 3123.88,3499.36 3155.57,3531.05 v1@3155.57,3563.28 ; J2_A1.32@3151.68,3647.12 3155.36,3643.44 3155.36,3564.11 v1(3157.66,3561.81)
  Bottom Layer w10: C77_A1.1@3107.53,3648.58 3107.53,3611.94 v1(3157.66,3561.81)
  Bottom Layer w12: R48_A1.1@2455.94,3138.62 2469.66,3152.33 2469.66,3217.69 2647.98,3396.01 2952.09,3396.01 3051.43,3495.36 3119.88,3495.36 3155.57,3531.05 v1@3155.57,3561.81
  other v1: 2396.24,2958.98 2396.24,2992.16 2396.24,3025.35 2396.24,3058.53 2396.24,3091.71 2396.24,3124.9 2396.24,3158.08
CELL3_A2: C77_A2.1 J2_A2.32 R42_A2.1 R45_A2.1 R48_A2.1 R52_A2.1 R132_A2.1 | length 1383.5
  Top Layer w10: R132_A2.1@5267.19,3431.26 5267.19,3435.19 5331.36,3499.36 5418.9,3499.36 5450.59,3531.05 v1@5450.59,3563.28 ; J2_A2.32@5446.7,3647.12 5450.38,3643.44 5450.38,3564.11 v1(5452.67,3561.81)
  Bottom Layer w10: C77_A2.1@5402.54,3648.58 5402.54,3611.94 v1(5452.67,3561.81)
  Bottom Layer w12: R48_A2.1@4750.96,3138.62 4764.67,3152.33 4764.67,3213.82 4946.87,3396.01 5247.1,3396.01 5346.45,3495.36 5414.9,3495.36 5450.59,3531.05 v1@5450.59,3561.81
  other v1: 4691.26,2958.98 4691.26,2992.16 4691.26,3025.35 4691.26,3058.53 4691.26,3091.71 4691.26,3124.9 4691.26,3158.08
CELL3_A3: C77_A3.1 J2_A3.32 R42_A3.1 R45_A3.1 R48_A3.1 R52_A3.1 R132_A3.1 | length 1456.5
  Top Layer w10: R132_A3.1@7603.79,3434.46 7603.79,3464.66 7609.65,3470.52 7645.1,3470.52 7677.15,3502.57 7755.49,3502.57 7787.18,3534.26 v1@7787.18,3566.49 ; J2_A3.32@7783.29,3650.33 7786.97,3646.65 7786.97,3567.32 v1(7789.27,3565.02)
  Bottom Layer w10: C77_A3.1@7739.14,3651.79 7739.14,3615.15 v1(7789.27,3565.02)
  Bottom Layer w12: R48_A3.1@7087.56,3141.83 7101.27,3155.54 7101.27,3315.3 7185.19,3399.22 7583.7,3399.22 7683.05,3498.57 7751.49,3498.57 7787.18,3534.26 v1@7787.18,3565.02
  other v1: 7027.85,2962.18 7027.85,2995.37 7027.85,3028.55 7027.85,3061.74 7027.85,3094.92 7027.85,3128.11 7027.85,3161.29
CELL3_A4: C77_A4.1 J2_A4.32 R42_A4.1 R45_A4.1 R48_A4.1 R52_A4.1 R132_A4.1 | length 1440.1
  Top Layer w10: R132_A4.1@9924.02,3431.26 9924.02,3461.45 9929.88,3467.31 9965.33,3467.31 9997.38,3499.36 10075.72,3499.36 10107.41,3531.05 v1@10107.41,3563.28 ; J2_A4.32@10103.52,3647.12 10107.2,3643.44 10107.2,3564.11 v1(10109.5,3561.81)
  Bottom Layer w10: C77_A4.1@10059.37,3648.58 10059.37,3611.94 v1(10109.5,3561.81)
  Bottom Layer w12: R48_A4.1@9407.79,3138.62 9421.5,3152.33 9421.5,3284.03 9533.48,3396.01 9903.93,3396.01 10003.28,3495.36 10071.72,3495.36 10107.41,3531.05 v1@10107.41,3561.81
  other v1: 9348.08,2958.98 9348.08,2992.16 9348.08,3025.35 9348.08,3058.53 9348.08,3091.71 9348.08,3124.9 9348.08,3158.08
CELL4_A1: C69_A1.1 J2_A1.12 R27_A1.1 R30_A1.1 R33_A1.1 R38_A1.1 R128_A1.1 | length 2356.1
  Top Layer w10: R128_A1.1@3029.04,3431.26 3029.04,3457.59 3052.94,3481.49 3145.37,3481.49 3194.94,3531.05 v1@3194.94,3563.28 ; J2_A1.12@3191.05,3647.12 3196.72,3641.45 3196.72,3564.11 v1(3199.02,3561.81)
  Bottom Layer w10: C69_A1.1@3161.96,3648.58 3161.96,3598.87 v1(3199.02,3561.81)
  Bottom Layer w12: R33_A1.1@2814.76,2183.48 2795.76,2202.48 2795.76,2263.3 2783.94,2275.12 2716.19,2275.12 2708.06,2283.24 2708.06,2568.52 2676.54,2600.04 2676.54,2893.29 2668.31,2901.52 2668.31,3369.11 2675.34,3376.14 2960.32,3376.14 3058.65,3474.47 3138.36,3474.47 3194.94,3531.05 v1@3194.94,3561.81
  other v1: 2750.57,2004.25 2750.57,2037.44 2750.57,2070.62 2750.57,2103.81 2750.57,2136.99 2750.57,2170.17 2750.57,2203.36
CELL4_A2: C69_A2.1 J2_A2.12 R27_A2.1 R30_A2.1 R33_A2.1 R38_A2.1 R128_A2.1 | length 2356.1
  Top Layer w10: R128_A2.1@5324.06,3431.26 5324.06,3457.59 5347.95,3481.49 5440.39,3481.49 5489.95,3531.05 v1@5489.95,3563.28 ; J2_A2.12@5486.07,3647.12 5491.74,3641.45 5491.74,3564.11 v1(5494.04,3561.81)
  Bottom Layer w10: C69_A2.1@5456.97,3648.58 5456.97,3598.87 v1(5494.04,3561.81)
  Bottom Layer w12: R33_A2.1@5109.78,2183.48 5090.78,2202.48 5090.78,2263.3 5078.96,2275.12 5011.2,2275.12 5003.08,2283.24 5003.08,2568.52 4971.56,2600.04 4971.56,2893.29 4963.33,2901.52 4963.33,3369.11 4970.36,3376.14 5255.34,3376.14 5353.67,3474.47 5433.38,3474.47 5489.95,3531.05 v1@5489.95,3561.81
  other v1: 5045.59,2004.25 5045.59,2037.44 5045.59,2070.62 5045.59,2103.81 5045.59,2136.99 5045.59,2170.17 5045.59,2203.36
CELL4_A3: C69_A3.1 J2_A3.12 R27_A3.1 R30_A3.1 R33_A3.1 R38_A3.1 R128_A3.1 | length 2356.1
  Top Layer w10: R128_A3.1@7660.66,3434.46 7660.66,3460.8 7684.55,3484.69 7776.99,3484.69 7826.55,3534.26 v1@7826.55,3566.49 ; J2_A3.12@7822.66,3650.33 7828.33,3644.66 7828.33,3567.32 v1(7830.63,3565.02)
  Bottom Layer w10: C69_A3.1@7793.57,3651.79 7793.57,3602.08 v1(7830.63,3565.02)
  Bottom Layer w12: R33_A3.1@7446.37,2186.69 7427.37,2205.69 7427.37,2266.5 7415.55,2278.32 7347.8,2278.32 7339.67,2286.45 7339.67,2571.73 7308.16,2603.25 7308.16,2896.49 7299.93,2904.72 7299.93,3372.32 7306.96,3379.35 7591.93,3379.35 7690.27,3477.68 7769.97,3477.68 7826.55,3534.26 v1@7826.55,3565.02
  other v1: 7382.18,2007.46 7382.18,2040.64 7382.18,2073.83 7382.18,2107.01 7382.18,2140.2 7382.18,2173.38 7382.18,2206.57
CELL4_A4: C69_A4.1 J2_A4.12 R27_A4.1 R30_A4.1 R33_A4.1 R38_A4.1 R128_A4.1 | length 2356.1
  Top Layer w10: R128_A4.1@9980.89,3431.26 9980.89,3457.59 10004.78,3481.49 10097.22,3481.49 10146.78,3531.05 v1@10146.78,3563.28 ; J2_A4.12@10142.89,3647.12 10148.56,3641.45 10148.56,3564.11 v1(10150.86,3561.81)
  Bottom Layer w10: C69_A4.1@10113.8,3648.58 10113.8,3598.87 v1(10150.86,3561.81)
  Bottom Layer w12: R33_A4.1@9766.6,2183.48 9747.6,2202.48 9747.6,2263.3 9735.78,2275.12 9668.03,2275.12 9659.9,2283.24 9659.9,2568.52 9628.39,2600.04 9628.39,2893.29 9620.16,2901.52 9620.16,3369.11 9627.19,3376.14 9912.16,3376.14 10010.5,3474.47 10090.2,3474.47 10146.78,3531.05 v1@10146.78,3561.81
  other v1: 9702.41,2004.25 9702.41,2037.44 9702.41,2070.62 9702.41,2103.81 9702.41,2136.99 9702.41,2170.17 9702.41,2203.36
CELL5_A1: C65_A1.1 J2_A1.33 R13_A1.1 R16_A1.1 R20_A1.1 R23_A1.1 R126_A1.1 | length 2014.6
  Top Layer w10: R126_A1.1@3085.91,3431.26 3112.24,3431.26 3118.09,3437.11 3118.09,3452.34 3129.37,3463.61 3160.96,3463.61 3234.3,3536.96 v1@3234.3,3561.81
  Top Layer w12: J2_A1.33@3230.42,3647.12 3238.2,3639.34 3238.2,3566.7 3240.38,3564.52 v1(3240.38,3561.81)
  Bottom Layer w12: R23_A1.1@2814.76,2498.57 2738.44,2498.57 2731.41,2505.6 2731.41,2573.28 2696.42,2608.27 2696.42,2901.52 2688.19,2909.75 2688.19,3349.23 2695.22,3356.26 2968.55,3356.26 3066.89,3454.6 3157.85,3454.6 3234.3,3531.05 3234.3,3542.48 3238.47,3546.64 3238.47,3559.9 v1(3240.38,3561.81) 3240.38,3624.59 C65_A1.1@3216.39,3648.58
  other v1: 2750.57,2319.21 2750.57,2352.4 2750.57,2385.58 2750.57,2418.77 2750.57,2451.95 2750.57,2485.14
CELL5_A2: C65_A2.1 J2_A2.33 R13_A2.1 R16_A2.1 R20_A2.1 R23_A2.1 R126_A2.1 | length 2014.6
  Top Layer w10: R126_A2.1@5380.93,3431.26 5407.25,3431.26 5413.11,3437.11 5413.11,3452.34 5424.38,3463.61 5455.98,3463.61 5529.32,3536.96 v1@5529.32,3561.81
  Top Layer w12: J2_A2.33@5525.44,3647.12 5533.22,3639.34 5533.22,3566.7 5535.4,3564.52 v1(5535.4,3561.81)
  Bottom Layer w12: R23_A2.1@5109.78,2498.57 5033.45,2498.57 5026.42,2505.6 5026.42,2573.28 4991.43,2608.27 4991.43,2901.52 4983.2,2909.75 4983.2,3349.23 4990.23,3356.26 5263.57,3356.26 5361.9,3454.6 5452.87,3454.6 5529.32,3531.05 5529.32,3542.48 5533.48,3546.64 5533.48,3559.9 v1(5535.4,3561.81) 5535.4,3624.59 C65_A2.1@5511.41,3648.58
  other v1: 5045.59,2319.21 5045.59,2352.4 5045.59,2385.58 5045.59,2418.77 5045.59,2451.95 5045.59,2485.14
CELL5_A3: C65_A3.1 J2_A3.33 R13_A3.1 R16_A3.1 R20_A3.1 R23_A3.1 R126_A3.1 | length 2014.6
  Top Layer w10: R126_A3.1@7717.52,3434.46 7743.85,3434.46 7749.71,3440.32 7749.71,3455.55 7760.98,3466.82 7792.57,3466.82 7865.92,3540.16 v1@7865.92,3565.02
  Top Layer w12: J2_A3.33@7862.03,3650.33 7869.81,3642.55 7869.81,3569.91 7871.99,3567.73 v1(7871.99,3565.02)
  Bottom Layer w12: R23_A3.1@7446.37,2501.78 7370.05,2501.78 7363.02,2508.81 7363.02,2576.49 7328.03,2611.48 7328.03,2904.73 7319.8,2912.96 7319.8,3352.44 7326.83,3359.47 7600.16,3359.47 7698.5,3457.81 7789.47,3457.81 7865.92,3534.26 7865.92,3545.69 7870.08,3549.85 7870.08,3563.11 v1(7871.99,3565.02) 7871.99,3627.79 C65_A3.1@7848,3651.79
  other v1: 7382.18,2322.42 7382.18,2355.6 7382.18,2388.79 7382.18,2421.97 7382.18,2455.16 7382.18,2488.34
CELL5_A4: C65_A4.1 J2_A4.33 R13_A4.1 R16_A4.1 R20_A4.1 R23_A4.1 R126_A4.1 | length 2014.6
  Top Layer w10: R126_A4.1@10037.75,3431.26 10064.08,3431.26 10069.94,3437.11 10069.94,3452.34 10081.21,3463.61 10112.8,3463.61 10186.15,3536.96 v1@10186.15,3561.81
  Top Layer w12: J2_A4.33@10182.26,3647.12 10190.04,3639.34 10190.04,3566.7 10192.22,3564.52 v1(10192.22,3561.81)
  Bottom Layer w12: R23_A4.1@9766.6,2498.57 9690.28,2498.57 9683.25,2505.6 9683.25,2573.28 9648.26,2608.27 9648.26,2901.52 9640.03,2909.75 9640.03,3349.23 9647.06,3356.26 9920.39,3356.26 10018.73,3454.6 10109.7,3454.6 10186.15,3531.05 10186.15,3542.48 10190.31,3546.64 10190.31,3559.9 v1(10192.22,3561.81) 10192.22,3624.59 C65_A4.1@10168.23,3648.58
  other v1: 9702.41,2319.21 9702.41,2352.4 9702.41,2385.58 9702.41,2418.77 9702.41,2451.95 9702.41,2485.14
CELL6_A1: C59_A1.1 J2_A1.13 R1_A1.1 R4_A1.1 R7_A1.1 R10_A1.1 R114_A1.1 | length 1681.9
  Top Layer w10: R114_A1.1@3142.78,3431.26 3169.1,3431.26 3174.96,3437.11 3174.96,3452.34 3182.5,3459.88 3202.5,3459.88 3262.55,3519.93
  Top Layer w12: 3261.85,3520.64 3261.85,3540.69 3281.74,3560.59 v1(3281.74,3561.81) 3281.74,3564.52 3277.57,3568.69 3277.57,3639.34 J2_A1.13@3269.79,3647.12
  Bottom Layer w12: R10_A1.1@2814.76,2813.66 2814.76,2884.06 2805.12,2893.7 2736.22,2893.7 2720.07,2909.85 2716.19,2909.85 2708.06,2917.98 2708.06,3200.61 2710.02,3202.57 2710.02,3329.36 2717.05,3336.39 2976.78,3336.39 3075.12,3434.72 3178.81,3434.72 3218.5,3474.41 3218.5,3487.08 3254.18,3522.76 3254.18,3534.25 v1(3281.74,3561.81) 3281.74,3564.52 3270.82,3575.45 C59_A1.1@3270.82,3648.58
  other v1: 2750.57,2634.17 2750.57,2667.36 2750.57,2700.54 2750.57,2733.73 2750.57,2766.91 2750.57,2800.1 2750.57,2833.28
CELL6_A2: C59_A2.1 J2_A2.13 R1_A2.1 R4_A2.1 R7_A2.1 R10_A2.1 R114_A2.1 | length 1681.9
  Top Layer w10: R114_A2.1@5437.8,3431.26 5464.12,3431.26 5469.98,3437.11 5469.98,3452.34 5477.52,3459.88 5497.52,3459.88 5557.57,3519.93
  Top Layer w12: 5556.86,3520.64 5556.86,3540.69 5576.76,3560.59 v1(5576.76,3561.81) 5576.76,3564.52 5572.59,3568.69 5572.59,3639.34 J2_A2.13@5564.81,3647.12
  Bottom Layer w12: R10_A2.1@5109.78,2813.66 5109.78,2884.06 5100.13,2893.7 5031.24,2893.7 5015.08,2909.85 5011.2,2909.85 5003.08,2917.98 5003.08,3200.61 5005.03,3202.57 5005.03,3329.36 5012.06,3336.39 5271.8,3336.39 5370.13,3434.72 5473.83,3434.72 5513.51,3474.41 5513.51,3487.08 5549.19,3522.76 5549.19,3534.25 v1(5576.76,3561.81) 5576.76,3564.52 5565.84,3575.45 C59_A2.1@5565.84,3648.58
  other v1: 5045.59,2634.17 5045.59,2667.36 5045.59,2700.54 5045.59,2733.73 5045.59,2766.91 5045.59,2800.1 5045.59,2833.28
CELL6_A3: C59_A3.1 J2_A3.13 R1_A3.1 R4_A3.1 R7_A3.1 R10_A3.1 R114_A3.1 | length 1681.9
  Top Layer w10: R114_A3.1@7774.39,3434.46 7800.72,3434.46 7806.58,3440.32 7806.58,3455.55 7814.12,3463.09 7834.11,3463.09 7894.16,3523.14
  Top Layer w12: 7893.46,3523.85 7893.46,3543.9 7913.36,3563.8 v1(7913.36,3565.02) 7913.36,3567.73 7909.18,3571.9 7909.18,3642.55 J2_A3.13@7901.4,3650.33
  Bottom Layer w12: R10_A3.1@7446.37,2816.87 7446.37,2887.27 7436.73,2896.91 7367.83,2896.91 7351.68,2913.06 7347.8,2913.06 7339.67,2921.19 7339.67,3203.82 7341.63,3205.78 7341.63,3332.57 7348.66,3339.6 7608.4,3339.6 7706.73,3437.93 7810.42,3437.93 7850.11,3477.62 7850.11,3490.28 7885.79,3525.97 7885.79,3537.46 v1(7913.36,3565.02) 7913.36,3567.73 7902.43,3578.65 C59_A3.1@7902.43,3651.79
  other v1: 7382.18,2637.38 7382.18,2670.57 7382.18,2703.75 7382.18,2736.93 7382.18,2770.12 7382.18,2803.3 7382.18,2836.49
CELL6_A4: C59_A4.1 J2_A4.13 R1_A4.1 R4_A4.1 R7_A4.1 R10_A4.1 R114_A4.1 | length 1681.9
  Top Layer w10: R114_A4.1@10094.62,3431.26 10120.95,3431.26 10126.81,3437.11 10126.81,3452.34 10134.35,3459.88 10154.34,3459.88 10214.39,3519.93
  Top Layer w12: 10213.69,3520.64 10213.69,3540.69 10233.59,3560.59 v1(10233.59,3561.81) 10233.59,3564.52 10229.41,3568.69 10229.41,3639.34 J2_A4.13@10221.63,3647.12
  Bottom Layer w12: R10_A4.1@9766.6,2813.66 9766.6,2884.06 9756.96,2893.7 9688.06,2893.7 9671.91,2909.85 9668.03,2909.85 9659.9,2917.98 9659.9,3200.61 9661.86,3202.57 9661.86,3329.36 9668.89,3336.39 9928.63,3336.39 10026.96,3434.72 10130.65,3434.72 10170.34,3474.41 10170.34,3487.08 10206.02,3522.76 10206.02,3534.25 v1(10233.59,3561.81) 10233.59,3564.52 10222.66,3575.45 C59_A4.1@10222.66,3648.58
  other v1: 9702.41,2634.17 9702.41,2667.36 9702.41,2700.54 9702.41,2733.73 9702.41,2766.91 9702.41,2800.1 9702.41,2833.28
CELL7_A1: C56_A1.1 J2_A1.34 R70_A1.1 R73_A1.1 R77_A1.1 R81_A1.1 R104_A1.1 | length 1114.3
  Top Layer w10: R104_A1.1@3199.65,3431.26 3199.65,3435.19 3206.46,3442 3209.9,3442 3288.54,3520.64 3288.54,3527.24 v1(3323.11,3561.81) 3323.11,3565.06 3317.94,3570.23 3317.94,3638.34 J2_A1.34@3309.16,3647.12
  Bottom Layer w10: 3083.38,3414.85 3198.3,3414.85 3257.86,3474.41 3257.86,3499.75 3319.93,3561.81 v1(3323.11,3561.81) 3324.18,3562.89 3324.18,3647.51 C56_A1.1@3325.25,3648.58
  Bottom Layer w12: R70_A1.1@2814.76,3128.75 2814.76,3212.87 2915.75,3313.86 2982.39,3313.86 3083.38,3414.85
  other v1: 2750.57,2949.13 2750.57,2982.32 2750.57,3015.5 2750.57,3048.69 2750.57,3081.87 2750.57,3115.06 2750.57,3148.24
CELL7_A2: C56_A2.1 J2_A2.34 R70_A2.1 R73_A2.1 R77_A2.1 R81_A2.1 R104_A2.1 | length 1114.3
  Top Layer w10: R104_A2.1@5494.66,3431.26 5494.66,3435.19 5501.47,3442 5504.92,3442 5583.55,3520.64 5583.55,3527.24 v1(5618.12,3561.81) 5618.12,3565.06 5612.96,3570.23 5612.96,3638.34 J2_A2.34@5604.18,3647.12
  Bottom Layer w10: 5378.4,3414.85 5493.32,3414.85 5552.88,3474.41 5552.88,3499.75 5614.94,3561.81 v1(5618.12,3561.81) 5619.19,3562.89 5619.19,3647.51 C56_A2.1@5620.27,3648.58
  Bottom Layer w12: R70_A2.1@5109.78,3128.75 5109.78,3212.87 5210.77,3313.86 5277.41,3313.86 5378.4,3414.85
  other v1: 5045.59,2949.13 5045.59,2982.32 5045.59,3015.5 5045.59,3048.69 5045.59,3081.87 5045.59,3115.06 5045.59,3148.24
CELL7_A3: C56_A3.1 J2_A3.34 R70_A3.1 R73_A3.1 R77_A3.1 R81_A3.1 R104_A3.1 | length 1114.3
  Top Layer w10: R104_A3.1@7831.26,3434.46 7831.26,3438.4 7838.07,3445.21 7841.52,3445.21 7920.15,3523.85 7920.15,3530.45 v1(7954.72,3565.02) 7954.72,3568.27 7949.55,3573.44 7949.55,3641.55 J2_A3.34@7940.77,3650.33
  Bottom Layer w10: 7714.99,3418.06 7829.92,3418.06 7889.48,3477.62 7889.48,3502.96 7951.54,3565.02 v1(7954.72,3565.02) 7955.79,3566.09 7955.79,3650.71 C56_A3.1@7956.86,3651.79
  Bottom Layer w12: R70_A3.1@7446.37,3131.96 7446.37,3216.08 7547.36,3317.07 7614,3317.07 7714.99,3418.06
  other v1: 7382.18,2952.34 7382.18,2985.53 7382.18,3018.71 7382.18,3051.9 7382.18,3085.08 7382.18,3118.27 7382.18,3151.45
CELL7_A4: C56_A4.1 J2_A4.34 R70_A4.1 R73_A4.1 R77_A4.1 R81_A4.1 R104_A4.1 | length 1114.3
  Top Layer w10: R104_A4.1@10151.49,3431.26 10151.49,3435.19 10158.3,3442 10161.75,3442 10240.38,3520.64 10240.38,3527.24 v1(10274.95,3561.81) 10274.95,3565.06 10269.78,3570.23 10269.78,3638.34 J2_A4.34@10261,3647.12
  Bottom Layer w10: 10035.22,3414.85 10150.15,3414.85 10209.71,3474.41 10209.71,3499.75 10271.77,3561.81 v1(10274.95,3561.81) 10276.02,3562.89 10276.02,3647.51 C56_A4.1@10277.09,3648.58
  Bottom Layer w12: R70_A4.1@9766.6,3128.75 9766.6,3212.87 9867.59,3313.86 9934.23,3313.86 10035.22,3414.85
  other v1: 9702.41,2949.13 9702.41,2982.32 9702.41,3015.5 9702.41,3048.69 9702.41,3081.87 9702.41,3115.06 9702.41,3148.24
CELL8_A1: C50_A1.1 J2_A1.14 R56_A1.1 R59_A1.1 R63_A1.1 R67_A1.1 R100_A1.1 | length 2015.9
  Top Layer w10: R100_A1.1@3256.52,3431.26 3256.52,3435.19 3295.51,3474.19 3295.51,3494.93 3362.4,3561.81 v1(3364.47,3561.81) 3364.47,3565.06 3357.31,3572.22 3357.31,3638.34 J2_A1.14@3348.53,3647.12
  Bottom Layer w10: 3320,3523.52 3326.18,3523.52 v1(3364.47,3561.81) 3364.47,3565.06 3379.68,3580.28 C50_A1.1@3379.68,3648.58
  Bottom Layer w12: R67_A1.1@3149.11,2183.48 3149.11,2252.87 3142.08,2259.9 3072.49,2259.9 3039.3,2293.08 3039.3,2582.34 3024.53,2597.12 3024.53,2886.04 3019.8,2890.76 3019.8,2891.9 3005.38,2906.31 3005.38,3235.23 3154.17,3384.01 3194.16,3384.01 3276.74,3466.59 3276.74,3480.26 3320,3523.52
  other v1: 3104.9,2004.25 3104.9,2037.44 3104.9,2070.62 3104.9,2103.81 3104.9,2136.99 3104.9,2170.17 3104.9,2203.36
CELL8_A2: C50_A2.1 J2_A2.14 R56_A2.1 R59_A2.1 R63_A2.1 R67_A2.1 R100_A2.1 | length 2015.9
  Top Layer w10: R100_A2.1@5551.53,3431.26 5551.53,3435.19 5590.53,3474.19 5590.53,3494.93 5657.41,3561.81 v1(5659.48,3561.81) 5659.48,3565.06 5652.33,3572.22 5652.33,3638.34 J2_A2.14@5643.55,3647.12
  Bottom Layer w10: 5615.02,3523.52 5621.19,3523.52 v1(5659.48,3561.81) 5659.48,3565.06 5674.7,3580.28 C50_A2.1@5674.7,3648.58
  Bottom Layer w12: R67_A2.1@5444.12,2183.48 5444.12,2252.87 5437.09,2259.9 5367.5,2259.9 5334.32,2293.08 5334.32,2582.34 5319.54,2597.12 5319.54,2886.04 5314.82,2890.76 5314.82,2891.9 5300.4,2906.31 5300.4,3235.23 5449.18,3384.01 5489.17,3384.01 5571.75,3466.59 5571.75,3480.26 5615.02,3523.52
  other v1: 5399.92,2004.25 5399.92,2037.44 5399.92,2070.62 5399.92,2103.81 5399.92,2136.99 5399.92,2170.17 5399.92,2203.36
CELL8_A3: C50_A3.1 J2_A3.14 R56_A3.1 R59_A3.1 R63_A3.1 R67_A3.1 R100_A3.1 | length 2015.9
  Top Layer w10: R100_A3.1@7888.13,3434.46 7888.13,3438.4 7927.12,3477.4 7927.12,3498.13 7994.01,3565.02 v1(7996.08,3565.02) 7996.08,3568.27 7988.92,3575.43 7988.92,3641.55 J2_A3.14@7980.14,3650.33
  Bottom Layer w10: 7951.61,3526.73 7957.79,3526.73 v1(7996.08,3565.02) 7996.08,3568.27 8011.29,3583.48 C50_A3.1@8011.29,3651.79
  Bottom Layer w12: R67_A3.1@7780.72,2186.69 7780.72,2256.07 7773.69,2263.1 7704.1,2263.1 7670.92,2296.29 7670.92,2585.55 7656.14,2600.33 7656.14,2889.25 7651.41,2893.97 7651.41,2895.1 7637,2909.52 7637,3238.44 7785.78,3387.22 7825.77,3387.22 7908.35,3469.8 7908.35,3483.47 7951.61,3526.73
  other v1: 7736.51,2007.46 7736.51,2040.64 7736.51,2073.83 7736.51,2107.01 7736.51,2140.2 7736.51,2173.38 7736.51,2206.57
